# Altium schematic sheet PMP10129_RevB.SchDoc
size 431 x 279 mm; Date: Not shown in title block; ApprovedBy: Not shown in title block; CheckedBy: Not shown in title block; Author: Not shown in title block; CompanyName: Not shown in title block; Engineer: Not shown in title block; Organization: Not shown in title block; Address1: Not shown in title block; Address2: Not shown in title block; Address3: Not shown in title block; Address4: Not shown in title block; DocumentNumber: 1; Revision: Use project parameter SCH_Rev; SheetNumber: 1; SheetTotal: 1; PageSetup: Record=PageOptions¦CenterHorizontal=True¦CenterVertical=True¦PrintScale=1.00¦XCorrection=1.00¦YCorrection=1.00¦PrintKind=0¦BorderSize=5000000¦LeftOffset=0¦BottomOffset=0¦Orientation=2¦PaperLength=1000¦PaperWidth=1000¦Scale=100¦PaperSource=15¦PrintQuality=600¦MediaType=1¦DitherType=10¦PaperKind=Letter¦PrintScaleMode=1
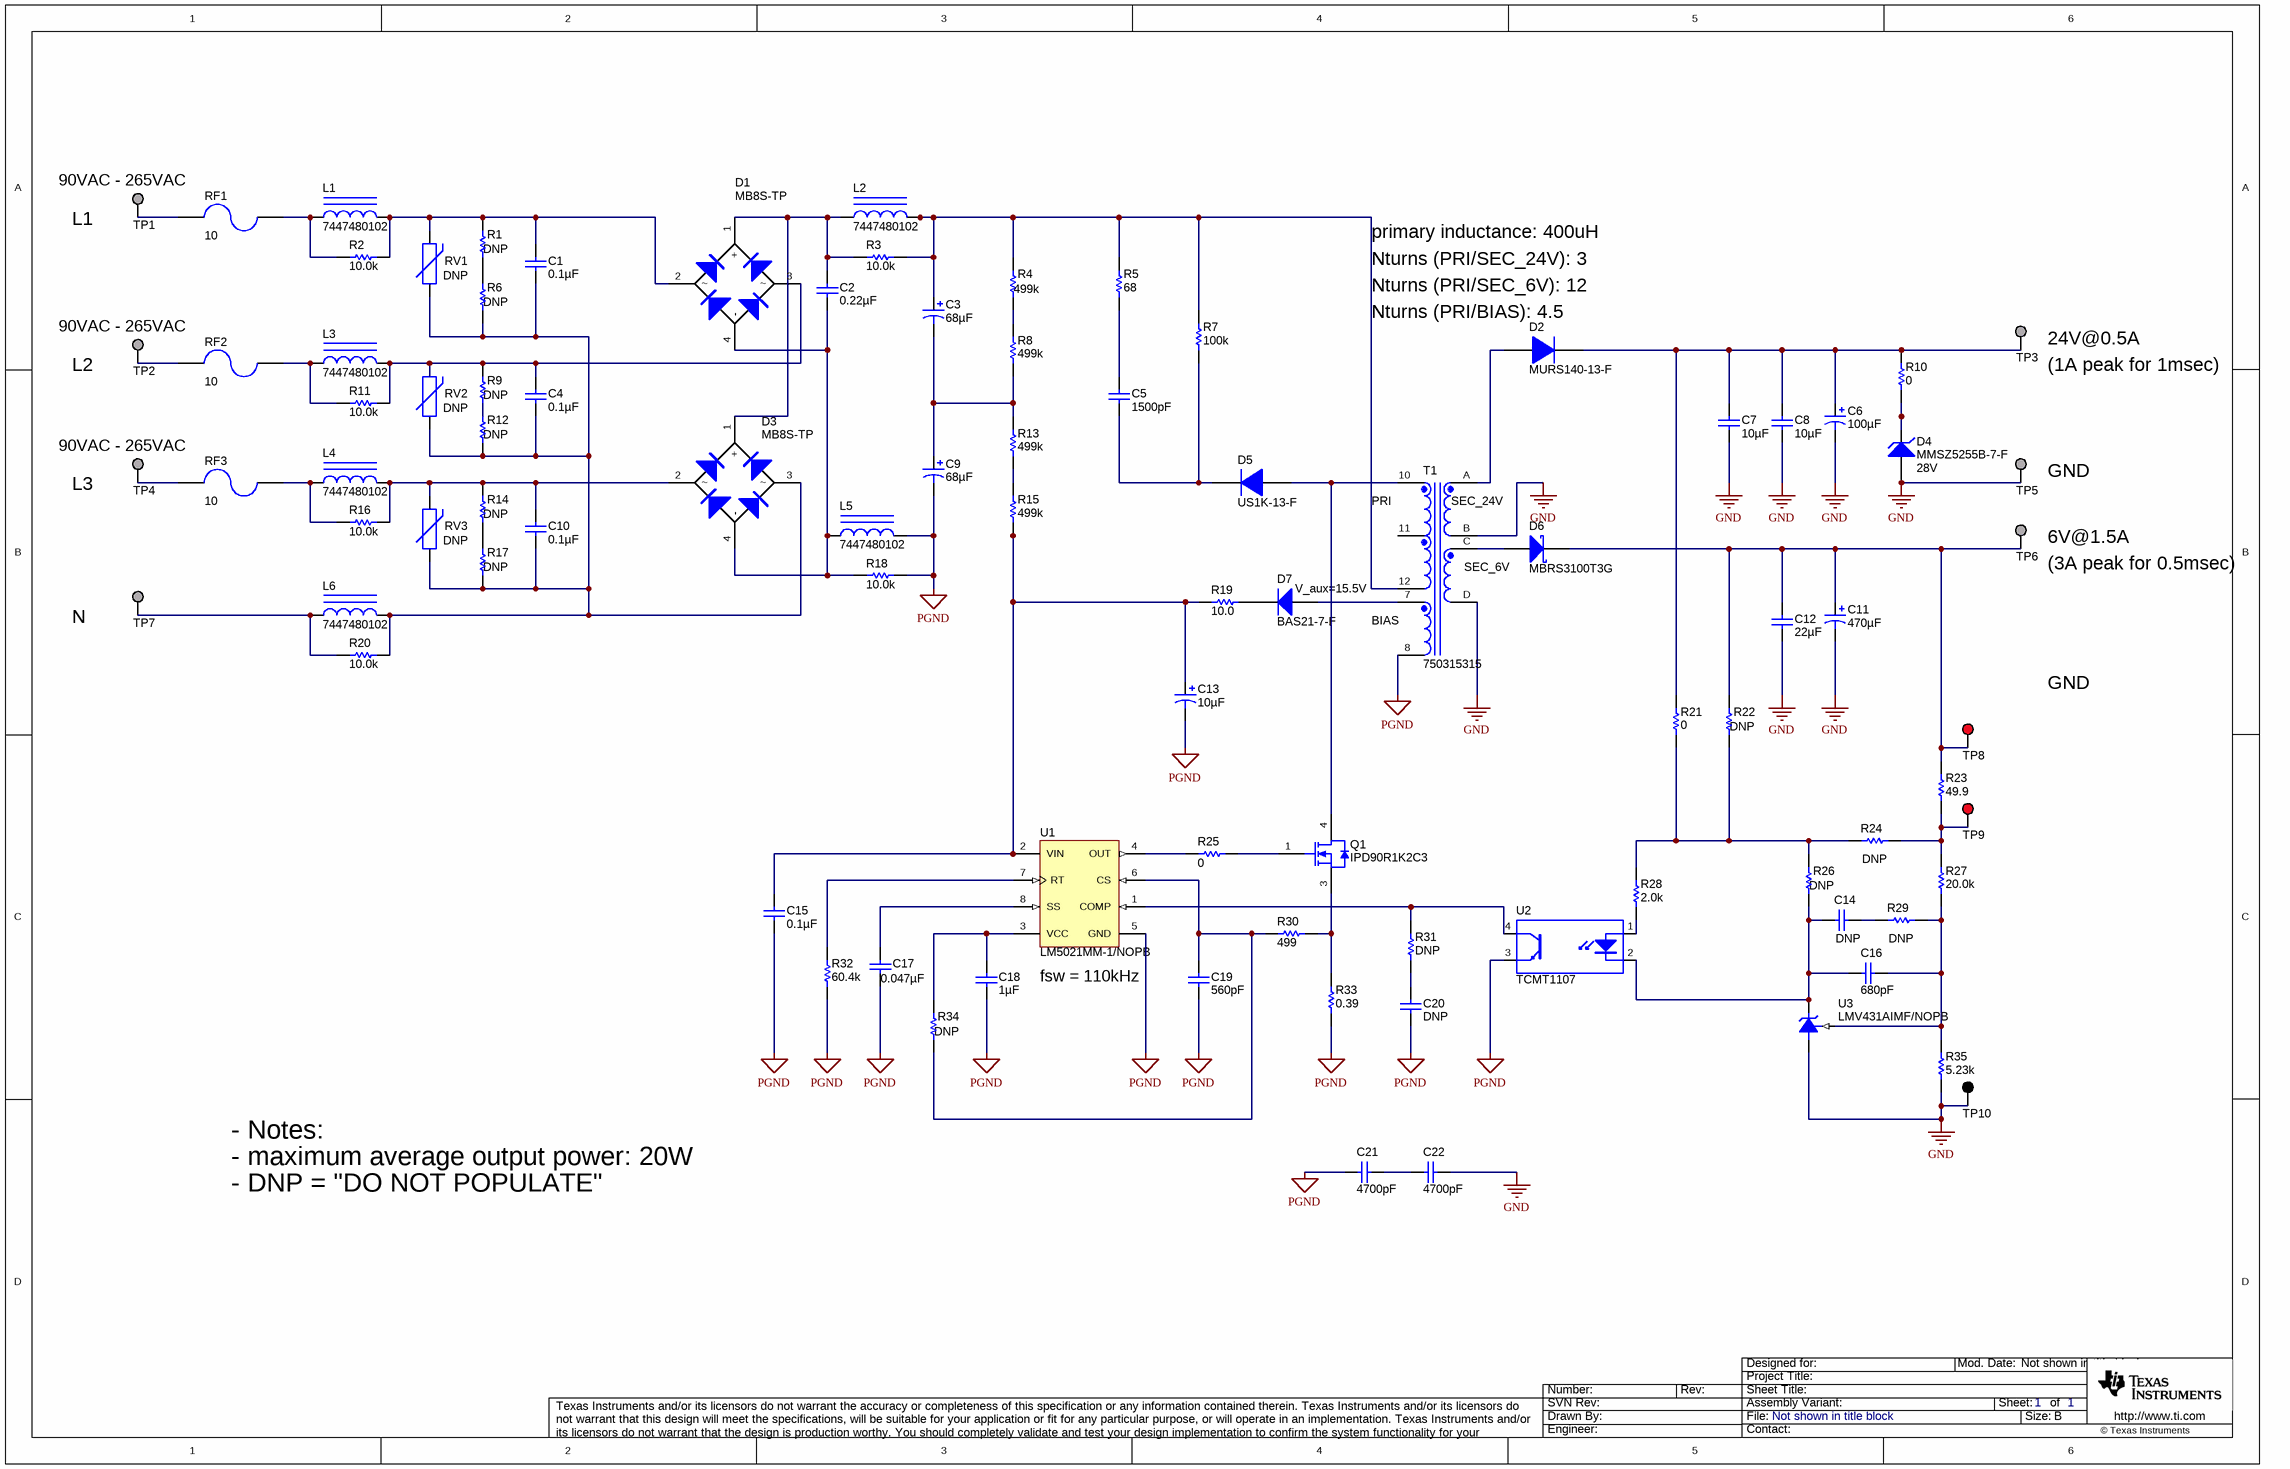
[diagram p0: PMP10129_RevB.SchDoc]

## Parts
C1  ValueDisplayed: 0.1µF  [B32921_1300x1200x600]  (hidden comment: B32921C3104M)
C2  ValueDisplayed: 0.22µF  [B32653_2650x2050x1100]  (hidden comment: B32653A224J)
C3  ValueDisplayed: 68µF  [KXG_1800x3150]  (hidden comment: EKXG401ELL680MM25S)
C4  ValueDisplayed: 0.1µF  [B32921_1300x1200x600]  (hidden comment: B32921C3104M)
C5  ValueDisplayed: 1500pF  [1206]  (hidden comment: C3216C0G2J152J)
C6  ValueDisplayed: 100µF  [SM_RADIAL_F]  (hidden comment: EEE-FK1H101P)
C7  ValueDisplayed: 10µF  [1210_280]  (hidden comment: C3225X7R1H106M250AC)
C8  ValueDisplayed: 10µF  [1210_280]  (hidden comment: C3225X7R1H106M250AC)
C9  ValueDisplayed: 68µF  [KXG_1800x3150]  (hidden comment: EKXG401ELL680MM25S)
C10  ValueDisplayed: 0.1µF  [B32921_1300x1200x600]  (hidden comment: B32921C3104M)
C11  ValueDisplayed: 470µF  [SM_RADIAL_F]  (hidden comment: EEE-FK1A471P)
C12  ValueDisplayed: 22µF  [1210_280]  (hidden comment: C3225X7R1C226K250AC)
C13  ValueDisplayed: 10µF  [SM_RADIAL_D]  (hidden comment: EEE-FC1H100P)
C14  value DNP  [0603_HV]  (hidden comment: Used in BOM report)
C15  ValueDisplayed: 0.1µF  [0603]  (hidden comment: C1608X7R1H104K)
C16  ValueDisplayed: 680pF  [0603]  (hidden comment: C0603C681K5RACTU)
C17  ValueDisplayed: 0.047µF  [0603]  (hidden comment: C1608X7R1H473K)
C18  ValueDisplayed: 1µF  [0805_HV]  (hidden comment: 08055C105KAT2A)
C19  ValueDisplayed: 560pF  [0603]  (hidden comment: GRM1885C1H561JA01D)
C20  value DNP  [0603_HV]  (hidden comment: Used in BOM report)
C21  ValueDisplayed: 4700pF  [VY2_1250x500x1650]  (hidden comment: VY2472M49Y5US63V7)
C22  ValueDisplayed: 4700pF  [VY2_1250x500x1650]  (hidden comment: VY2472M49Y5US63V7)
D1  MB8S-TP  [MBS-1]
D2  MURS140-13-F  [SMB]
D3  MB8S-TP  [MBS-1]
D4  MMSZ5255B-7-F  value 28V  [SOD-123]
D5  US1K-13-F  [SMA]
D6  MBRS3100T3G  [SMC]
D7  BAS21-7-F  [SOT-23]
L1  7447480102  [WE_TI_1014]
L2  7447480102  [WE_TI_1014]
L3  7447480102  [WE_TI_1014]
L4  7447480102  [WE_TI_1014]
L5  7447480102  [WE_TI_1014]
L6  7447480102  [WE_TI_1014]
Q1  IPD90R1K2C3  [DPAK]
R1  value DNP  [0805_HV]  (hidden comment: Used in BOM report)
R2  ValueDisplayed: 10.0k  [0805_HV]  (hidden comment: CRCW080510K0FKEA)
R3  ValueDisplayed: 10.0k  [0805_HV]  (hidden comment: CRCW080510K0FKEA)
R4  ValueDisplayed: 499k  [1206]  (hidden comment: CRCW1206499KFKEA)
R5  ValueDisplayed: 68  [2010]  (hidden comment: CRCW201068R0JNEF)
R6  value DNP  [0805_HV]  (hidden comment: Used in BOM report)
R7  ValueDisplayed: 100k  [2010]  (hidden comment: CRCW2010100KFKEF)
R8  ValueDisplayed: 499k  [1206]  (hidden comment: CRCW1206499KFKEA)
R9  value DNP  [0805]  (hidden comment: Used in BOM report)
R10  ValueDisplayed: 0  [0805_HV]  (hidden comment: CRCW08050000Z0EAHP)
R11  ValueDisplayed: 10.0k  [0805_HV]  (hidden comment: CRCW080510K0FKEA)
R12  value DNP  [0805_HV]  (hidden comment: Used in BOM report)
R13  ValueDisplayed: 499k  [1206]  (hidden comment: CRCW1206499KFKEA)
R14  value DNP  [0805_HV]  (hidden comment: Used in BOM report)
R15  ValueDisplayed: 499k  [1206]  (hidden comment: CRCW1206499KFKEA)
R16  ValueDisplayed: 10.0k  [0805_HV]  (hidden comment: CRCW080510K0FKEA)
R17  value DNP  [0805_HV]  (hidden comment: Used in BOM report)
R18  ValueDisplayed: 10.0k  [0805_HV]  (hidden comment: CRCW080510K0FKEA)
R19  ValueDisplayed: 10.0  [0805_HV]  (hidden comment: CRCW080510R0FKEA)
R20  ValueDisplayed: 10.0k  [0805_HV]  (hidden comment: CRCW080510K0FKEA)
R21  ValueDisplayed: 0  [0603]  (hidden comment: CRCW06030000Z0EA)
R22  value DNP  [0603_HV]  (hidden comment: Used in BOM report)
R23  ValueDisplayed: 49.9  [0603]  (hidden comment: CRCW060349R9FKEA)
R24  value DNP  [0603_HV]  (hidden comment: Used in BOM report)
R25  ValueDisplayed: 0  [0805_HV]  (hidden comment: CRCW08050000Z0EA)
R26  value DNP  [0603_HV]  (hidden comment: Used in BOM report)
R27  ValueDisplayed: 20.0k  [0603]  (hidden comment: CRCW060320K0FKEA)
R28  ValueDisplayed: 2.0k  [0603]  (hidden comment: CRCW06032K00JNEA)
R29  value DNP  [0603_HV]  (hidden comment: Used in BOM report)
R30  ValueDisplayed: 499  [0603]  (hidden comment: RT0603DRE07499RL)
R31  value DNP  [0603_HV]  (hidden comment: Used in BOM report)
R32  ValueDisplayed: 60.4k  [0603]  (hidden comment: CRCW060360K4FKEA)
R33  ValueDisplayed: 0.39  [1206]  (hidden comment: ERJ-8RQFR39V)
R34  value DNP  [0603_HV]  (hidden comment: Used in BOM report)
R35  ValueDisplayed: 5.23k  [0603]  (hidden comment: CRCW06035K23FKEA)
RF1  ValueDisplayed: 10  [RES_PWR4522]  (hidden comment: FW20A10R0JACT-ND)
RF2  ValueDisplayed: 10  [RES_PWR4522]  (hidden comment: FW20A10R0JACT-ND)
RF3  ValueDisplayed: 10  [RES_PWR4522]  (hidden comment: FW20A10R0JACT-ND)
RV1  value DNP  [VAR_S10K275E2]  (hidden comment: S10K275E2)
RV2  value DNP  [VAR_S10K275E2]  (hidden comment: S10K275E2)
RV3  value DNP  [VAR_S10K275E2]  (hidden comment: S10K275E2)
T1  750315315  [Wurth_750315315]
TP1  Suggest using a net name here  [Keystone1503-2]  (value not drawn)
TP2  Suggest using a net name here  [Keystone1503-2]  (value not drawn)
TP3  Suggest using a net name here  [Keystone1503-2]  (value not drawn)
TP4  Suggest using a net name here  [Keystone1503-2]  (value not drawn)
TP5  Suggest using a net name here  [Keystone1503-2]  (value not drawn)
TP6  Suggest using a net name here  [Keystone1503-2]  (value not drawn)
TP7  Suggest using a net name here  [Keystone1503-2]  (value not drawn)
TP8  5000  [Keystone5000]  (value not drawn)
TP9  5000  [Keystone5000]  (value not drawn)
TP10  5001  [Keystone5001]  (value not drawn)
U1  LM5021MM-1/NOPB  [MUA08A_N]
U2  TCMT1107  [SOP-4]
U3  LMV431AIMF/NOPB  [MF03A_N]

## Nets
GND: C6.2(-) C7.2 C8.2 C11.2(-) C12.2 C22.2 D4.2(A) R35.1 T1.B T1.D TP5.1 TP10.1 U3.3(A)
PGND: C9.2(-) C13.2(-) C15.2 C17.2 C18.2 C19.2 C20.2 C21.1 L5.2 R18.2 R32.1 R33.1 T1.8 U1.5(GND) U2.3(E)
NetC1_1: C1.1 D1.2 L1.2 R1.2 R2.2 RV1.2
NetC1_2: C1.2 C4.2 C10.2 D3.3 L6.2 R6.1 R12.1 R17.1 R20.2 RV1.1 RV2.1 RV3.1
NetC2_1: C2.1 D1.1(+) D3.1(+) L2.1 R3.1
NetC2_2: C2.2 D1.4(-) D3.4(-) L5.1 R18.1
NetC3_1: C3.1(+) L2.2 R3.2 R4.2 R5.2 R7.2 T1.12
NetC3_2: C3.2(-) C9.1(+) R8.1 R13.2
NetC4_1: C4.1 D1.3 L3.2 R9.2 R11.2 RV2.2
NetC5_1: C5.1 R5.1
NetC5_2: C5.2 D5.1(K) R7.1
NetC6_1: C6.1(+) C7.1 C8.1 D2.1(K) R10.2 R21.2 TP3.1
NetC10_1: C10.1 D3.2 L4.2 R14.2 R16.2 RV3.2
NetC11_1: C11.1(+) C12.1 D6.1(K) R22.2 R23.2 TP6.1 TP8.1
NetC13_1: C13.1(+) C15.1 R15.1 R19.1 U1.2(VIN)
NetC14_1: C14.1 R29.1
NetC14_2: C14.2 C16.2 R26.1 U2.2(K) U3.2(K)
NetC16_1: C16.1 R27.1 R29.2 R35.2 U3.1(REF)
NetC17_1: C17.1 U1.8(SS)
NetC18_1: C18.1 R34.2 U1.3(VCC)
NetC19_1: C19.1 R30.1 R34.1 U1.6(CS)
NetC20_1: C20.1 R31.1
NetC21_2: C21.2 C22.1
NetD2_2: D2.2(A) T1.A
NetD4_1: D4.1(K) R10.1
NetD5_2: D5.2(A) Q1.4(D) T1.10
NetD6_2: D6.2(A) T1.C
NetD7_1: D7.1(A) T1.7
NetD7_3: D7.3(K) R19.2
NetL1_1: L1.1 R2.1 RF1.1
NetL3_1: L3.1 R11.1 RF2.1
NetL4_1: L4.1 R16.1 RF3.1
NetL6_1: L6.1 R20.1 TP7.1
NetQ1_1: Q1.1(G) R25.2
NetQ1_3: Q1.3(S) R30.2 R33.2
NetR1_1: R1.1 R6.2
NetR4_1: R4.1 R8.2
NetR9_1: R9.1 R12.2
NetR13_1: R13.1 R15.2
NetR14_1: R14.1 R17.2
NetR21_1: R21.1 R22.1 R24.1 R26.2 R28.2
NetR23_1: R23.1 R24.2 R27.2 TP9.1
NetR25_1: R25.1 U1.4(OUT)
NetR28_1: R28.1 U2.1(A)
NetR31_2: R31.2 U1.1(COMP) U2.4(C)
NetR32_2: R32.2 U1.7(RT)
NetRF1_2: RF1.2 TP1.1
NetRF2_2: RF2.2 TP2.1
NetRF3_2: RF3.2 TP4.1

Not connected (* = marked no-connect by the designer): T1 11

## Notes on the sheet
- (near TP1) 90VAC - 265VAC
- (near TP1) L1
- primary inductance: 400uH
- Nturns (PRI/SEC_24V): 3
- Nturns (PRI/SEC_6V): 12
- (near TP2) 90VAC - 265VAC
- (near D2) Nturns (PRI/BIAS): 4.5
- (near TP3) 24V@0.5A
- (near TP2) L2
- (near TP3) (1A peak for 1msec)
- (near TP4) 90VAC - 265VAC
- (near TP4) L3
- (near TP5) GND
- (near T1) PRI
- (near T1) SEC_24V
- (near TP6) 6V@1.5A
- N
- (near D7) V_aux=15.5V
- (near T1) BIAS
- (near T1) SEC_6V
- (near TP6) (3A peak for 0.5msec)
- GND
- fsw = 110kHz
- - Notes:
- - maximum average output power: 20W
- - DNP = "DO NOT POPULATE"

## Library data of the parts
C1 C4 C10 = B32921C3104M: CAP, Film, 0.1 µF, 305 V, +/- 20%, TH; Manufacturer: EPCOS Inc; Polarized: N; CompType: Capacitor; Value: 0.1uF; U/M: EA; Cap_F: 0.0000001; Tolerance_%: 20; Value1: Unknown; VDC_V: 305; Value2: 305V; TaMin_C: -40; TaMax_C: 110; Cap_Case: 13x12x6mm
C2 = B32653A224J: CAP, Film, 0.22 µF, 1000 V, +/- 5%, TH; Manufacturer: EPCOS Inc; Polarized: N; CompType: Capacitor; Value: 0.22uF; U/M: EA; Cap_F: 0.00000022; Tolerance_%: 5; Value1: Unknown; VDC_V: 1000; Value2: 1000V; TaMin_C: -55; TaMax_C: 110; Cap_Case: 26.5x20.5x11mm
C3 C9 = EKXG451ELL680MMN3S: CAP, AL, 68 µF, 400 V, +/- 20%,  ohm, TH; Manufacturer: Chemi-Con; Polarized: Y; CompType: Capacitor; Value: 68uF; U/M: EA; Cap_F: 0.000068; Tolerance_%: 20; Value1: Unknown; VDC_V: 450; Value2: 400V; IRMS_A: 0.63; TaMin_C: -25; TaMax_C: 105; Cap_Case: 18x31.5mm
C5 = C3216C0G2J152J: CAP, CERM, 1500 pF, 630 V, +/- 5%, C0G/NP0, 1206; Manufacturer: TDK; Polarized: N; CompType: Capacitor; Value: 1500pF; U/M: EA; Cap_F: 0.0000000015; Tolerance_%: 5; ESR_ohm: 0.0467; Value1: 0.0467 ohm; VDC_V: 630; Value2: 630V; TaMin_C: -55; TaMax_C: 125
C6 = EEE-FK1H101P: CAP, AL, 100 µF, 50 V, +/- 20%, 0.34 ohm, SMD; Manufacturer: Panasonic; Polarized: Y; CompType: Capacitor; Value: 100uF; U/M: EA; Cap_F: 0.0001; Tolerance_%: 20; VDC_V: 50; Value2: 50V; ESR_ohm: 0.34; IRMS_A: 0.35; TaMin_C: -55; TaMax_C: 105; Cap_Case: F
C7 C8 = C3225X7R1H106M250AC: CAP, CERM, 10 µF, 50 V, +/- 20%, X7R, 1210; Manufacturer: TDK; Polarized: N; CompType: Capacitor; Value: 10uF; U/M: EA; Cap_F: 0.00001; Tolerance_%: 20; Value1: Unknown; VDC_V: 50; Value2: 50V; TaMin_C: -55; TaMax_C: 125; Cap_Case: 1210
C11 = EEE-FK1A471P: CAP, AL, 470 µF, 10 V, +/- 20%, 0.16 ohm, SMD; Manufacturer: Panasonic; Polarized: Y; CompType: Capacitor; Value: 470uF; U/M: EA; Cap_F: 0.00047; Tolerance_%: 20; VDC_V: 10; Value2: 10V; ESR_ohm: 0.16; IRMS_A: 0.6; TaMin_C: -55; TaMax_C: 105; Cap_Case: F
C12 = C3225X7R1C226K250AC: CAP, CERM, 22 µF, 16 V, +/- 10%, X7R, 1210; Manufacturer: TDK; Polarized: N; CompType: Capacitor; Value: 22uF; U/M: EA; Cap_F: 0.000022; Tolerance_%: 10; Value1: Unknown; VDC_V: 16; Value2: 16V; TaMin_C: -55; TaMax_C: 125; Cap_Case: 1210
C13 = EEE-FC1H100P: CAP, AL, 10 µF, 50 V, +/- 20%, 2 ohm, SMD; Manufacturer: Panasonic; Polarized: Y; CompType: Capacitor; Value: 10uF; U/M: EA; Cap_F: 0.00001; Tolerance_%: 20; Value1: 2 ohm; VDC_V: 50; Value2: 50V; ESR_ohm: 2; IRMS_A: 0.07; TaMin_C: -40; TaMax_C: 105; Cap_Case: D
C14 C20 = Capacitor: CAP, CERM, xxxF, xxV, [TempCo], xx%, [PackageReference]; Polarized: N; U/M: EA
C15 = C1608X7R1H104K: CAP, CERM, 0.1 µF, 50 V, +/- 10%, X7R, 0603; Manufacturer: TDK; Polarized: N; CompType: Capacitor; Value: 0.1uF; U/M: EA; Cap_F: 0.0000001; Tolerance_%: 10; ESR_ohm: 0.017; Value1: 0.017 ohm; VDC_V: 50; Value2: 50V; TaMin_C: -55; TaMax_C: 125
C16 = C0603C681K5RACTU: CAP, CERM, 680 pF, 50 V, +/- 10%, X7R, 0603; Manufacturer: Kemet; Polarized: N; CompType: Capacitor; Value: 680pF; U/M: EA; Cap_F: 0.00000000068; Tolerance_%: 10; Value1: Unknown; VDC_V: 50; Value2: 50V; TaMin_C: -55; TaMax_C: 125; AEC Category: Q200
C17 = C1608X7R1H473K: CAP, CERM, 0.047 µF, 50 V, +/- 10%, X7R, 0603; Manufacturer: TDK; Polarized: N; CompType: Capacitor; Value: 0.047uF; U/M: EA; Cap_F: 0.000000047; Tolerance_%: 10; ESR_ohm: 0.0234; Value1: 0.0234 ohm; VDC_V: 50; Value2: 50V; TaMin_C: -55; TaMax_C: 125
C18 = 08055C105KAT2A: CAP, CERM, 1 µF, 50 V, +/- 10%, X7R, 0805; Manufacturer: AVX; Polarized: N; CompType: Capacitor; Value: 1uF; U/M: EA; Cap_F: 0.000001; Tolerance_%: 10; Value1: Unknown; VDC_V: 50; Value2: 50V; TaMin_C: -55; TaMax_C: 125; Cap_Case: 0805
C19 = GRM1885C1H561JA01D: CAP, CERM, 560 pF, 50 V, +/- 5%, C0G/NP0, 0603; Manufacturer: MuRata; Polarized: N; CompType: Capacitor; Value: 560pF; U/M: EA; Cap_F: 0.00000000056; Tolerance_%: 5; Value1: Unknown; VDC_V: 50; Value2: 50V; TaMin_C: -55; TaMax_C: 125
C21 C22 = VY2472M49Y5US63V7: CAP, CERM, 4700 pF, 440 V, +/- 20%, Y5U, TH, 12.5x5mm; Manufacturer: Vishay-Bccomponents; Polarized: N; CompType: Capacitor; Value: 4700pF; U/M: EA; Cap_F: 0.0000000047; Tolerance_%: 20; Value1: Unknown; VDC_V: 440; Value2: 440V; TaMin_C: -40; TaMax_C: 125; Cap_Case: 12.5x5x16.5
D1 D3 = MB8S-TP: Diode, Switching-Bridge, 800 V, 0.5 A, 4-Pin TO269AA, Body 4.95 x 4.2 mm, Pitch 2.555 mm; Manufacturer: Micro Commercial Components; U/M: EA; Vf_V: 1; Value: 800V; Value1: 0.5A; Value2: 1V; Io_A: 0.5; Vr_V: 800; TJmax_C: 150
D2 = MURS140-13-F: Diode, Ultrafast, 400 V, 1 A, SMB; Manufacturer: Diodes Inc.; U/M: EA; Vf_V: 1.25; Value: 400V; Value1: 1A; Value2: 1.25V; Io_A: 1; Vr_V: 400; TJmax_C: 150; RJC_CperW: 13
D4 = MMSZ5255B-7-F: Diode, Zener, 28 V, 500 mW, SOD-123; Manufacturer: Diodes Inc.; SymbolCreator: a0412235; U/M: EA; Power_W: 0.5; Vz_V: 28; Value1: 0.5W; RJA_CperW: 350
D5 = US1K-13-F: Diode, Fast Rectifier, 800 V, 1 A, SMA; Manufacturer: Diodes Inc.; U/M: EA; Vf_V: 1.7; Value: 800V; Value1: 1A; Value2: 1.7V; Io_A: 1; Vr_V: 800; TJmax_C: 150
D6 = MBRS3100T3G: Diode, Schottky, 100 V, 3 A, SMC; Manufacturer: ON Semiconductor; U/M: EA; Vf_V: 0.62; Value: 100V; Value1: 3A; Value2: 0.62V; Io_A: 3; Vr_V: 100; TJmax_C: 150; RJC_CperW: 11
D7 = BAS21-7-F: Diode, Switching, 200 V, 0.2 A, SOT-23; Manufacturer: Diodes Inc.; U/M: EA; Vf_V: 1.25; Value: 200V; Value1: 0.2A; Value2: 1.25V; Io_A: 0.2; Vr_V: 200; TJmax_C: 150; RJC_CperW: 500
L1-L6 = 7447480471: Inductor, Wirewound, Ferrite, 470 µH, 1.15 A, 0.47 ohm, TH; Manufacturer: Wurth Elektronik; Value: 1000uH; ValueDisplayed: 1000µH; Imax_A: 1.15; Irms: 1.15A @ 40C rise; Isat: 1.15A @ 10% inductance drop; DCR_ohm: 0.47
Q1 = MOSFET_N_D4G1S3: MOSFET, N-CH, xxV, xxxA, DPAK; Manufacturer: Used in BOM report; U/M: EA
R1 R6 R9 R12 R14 R17 R22 R24 R26 R29 R31 R34 = Resistor: RES, xxx ohm, x%, xW, [PackageReference]; U/M: EA
R2 R3 R11 R16 R18 R20 = CRCW080510K0FKEA: RES, 10.0 k, 1%, 0.125 W, 0805; Manufacturer: Vishay-Dale; CompType: Resistor; Value: 10.0k; Res_ohm: 10000; Value_Code: 10k0; Tolerance_%: 1; Power_W: 0.125; Value2: 0.125W; VDC_V: 150; TempCo: 100 ppm/C; EIA_Code: E96; U/M: EA
R4 R8 R13 R15 = CRCW1206499KFKEA: RES, 499 k, 1%, 0.25 W, 1206; Manufacturer: Vishay-Dale; CompType: Resistor; Value: 499k; Res_ohm: 499000; Tolerance_%: 1; Power_W: 0.25; Value2: 0.25W; VDC_V: 200; TempCo: 100 ppm/C; EIA_Code: E96; U/M: EA
R5 = CRCW201068R0JNEF: RES, 68, 5%, 0.75 W, 2010; Manufacturer: Vishay-Dale; CompType: Resistor; Value: 68; Value_Code: 68R0; Tolerance_%: 5; Power_W: 0.75; Value2: 0.75W; VDC_V: 400; TempCo: 200 ppm/C; EIA_Code: E24; U/M: EA; AEC Category: Q200
R7 = CRCW2010100KFKEF: RES, 100 k, 1%, 0.75 W, 2010; Manufacturer: Vishay-Dale; CompType: Resistor; Value: 100k; Res_ohm: 100000; Tolerance_%: 1; Power_W: 0.75; Value2: 0.75W; VDC_V: 400; TempCo: 100 ppm/C; EIA_Code: E96; U/M: EA; AEC Category: Q200
R10 = CRCW08050000Z0EAHP: RES, 0, 5%, 0.333 W, 0805; Manufacturer: Vishay-Dale; CompType: Resistor; Value: 0; Value_Code: 0000; Tolerance_%: 5; Power_W: 0.333; Value2: 0.333W; TempCo: 200 ppm/C; EIA_Code: E24; U/M: EA
R19 = CRCW080510R0FKEA: RES, 10.0, 1%, 0.125 W, 0805; Manufacturer: Vishay-Dale; CompType: Resistor; Value: 10.0; Res_ohm: 10; Value_Code: 10R0; Tolerance_%: 1; Power_W: 0.125; Value2: 0.125W; VDC_V: 150; TempCo: 100 ppm/C; EIA_Code: E96; U/M: EA
R21 = CRCW06030000Z0EA: RES, 0, 5%, 0.1 W, 0603; Manufacturer: Vishay-Dale; CompType: Resistor; Value: 0; Value_Code: 0000; Tolerance_%: 5; Power_W: 0.1; Value2: 0.1W; VDC_V: 75; TempCo: 200 ppm/C; EIA_Code: E24; U/M: EA
R23 = CRCW060349R9FKEA: RES, 49.9, 1%, 0.1 W, 0603; Manufacturer: Vishay-Dale; CompType: Resistor; Value: 49.9; Value_Code: 49R9; Tolerance_%: 1; Power_W: 0.1; Value2: 0.1W; VDC_V: 75; TempCo: 100 ppm/C; EIA_Code: E96; U/M: EA
R25 = CRCW08050000Z0EA: RES, 0, 5%, 0.125 W, 0805; Manufacturer: Vishay-Dale; CompType: Resistor; Value: 0; Value_Code: 0000; Tolerance_%: 5; Power_W: 0.125; Value2: 0.125W; VDC_V: 150; TempCo: 200 ppm/C; EIA_Code: E24; U/M: EA
R27 = CRCW060320K0FKEA: RES, 20.0 k, 1%, 0.1 W, 0603; Manufacturer: Vishay-Dale; CompType: Resistor; Value: 20.0k; Res_ohm: 20000; Value_Code: 20k0; Tolerance_%: 1; Power_W: 0.1; Value2: 0.1W; VDC_V: 75; TempCo: 100 ppm/C; EIA_Code: E96; U/M: EA
R28 = CRCW06032K00JNEA: RES, 2.0 k, 5%, 0.1 W, 0603; Manufacturer: Vishay-Dale; CompType: Resistor; Value: 2.0k; Res_ohm: 2000; Value_Code: 2k00; Tolerance_%: 5; Power_W: 0.1; Value2: 0.1W; VDC_V: 75; TempCo: 200 ppm/C; EIA_Code: E24; U/M: EA
R30 = RT0603DRE07499RL: RES, 499, 0.5%, 0.1 W, 0603; Manufacturer: Yageo America; CompType: Resistor; Value: 499; Value_Code: 499R; Tolerance_%: 0.5; Power_W: 0.1; Value2: 0.1W; VDC_V: 75; TempCo: 50 ppm/C; EIA_Code: E192; U/M: EA
R32 = CRCW060360K4FKEA: RES, 60.4 k, 1%, 0.1 W, 0603; Manufacturer: Vishay-Dale; CompType: Resistor; Value: 60.4k; Res_ohm: 60400; Value_Code: 60k4; Tolerance_%: 1; Power_W: 0.1; Value2: 0.1W; VDC_V: 75; TempCo: 100 ppm/C; EIA_Code: E96; U/M: EA
R33 = ERJ-8RQFR39V: RES, 0.39, 1%, 0.25 W, 1206; Manufacturer: Panasonic; CompType: Resistor; Value: 0.39; Value_Code: R390; Tolerance_%: 1; Power_W: 0.25; Value2: 0.25W; TempCo: 250 ppm/C; EIA_Code: E96; U/M: EA; AEC Category: Q200
R35 = CRCW06035K23FKEA: RES, 5.23 k, 1%, 0.1 W, 0603; Manufacturer: Vishay-Dale; CompType: Resistor; Value: 5.23k; Res_ohm: 5230; Value_Code: 5k23; Tolerance_%: 1; Power_W: 0.1; Value2: 0.1W; VDC_V: 75; TempCo: 100 ppm/C; EIA_Code: E96; U/M: EA
RF1 = PWR4522AS10R0JA: RES, 10, 5%, 32W, Fusible, TH; Manufacturer: Bourns; SymbolCreator: a0412235; CompType: Fusible Resistor; Value: 10; Value_Code: 10R0; Tolerance_%: 5; Power_W: 3; Value2: 3W; TempCo: 90 ppm/C; EIA_Code: E24; U/M: EA
RF2 RF3 = PWR4522AS10R0JA: RES, 10, 5%, 2 W, Fusible, TH; Manufacturer: Bourns; SymbolCreator: a0412235; CompType: Fusible Resistor; Value: 10; Value_Code: 10R0; Tolerance_%: 5; Power_W: 3; Value2: 3W; TempCo: 90 ppm/C; EIA_Code: E24; U/M: EA
RV1-RV3 = S10K275E2: Varistor 275V RMS 10MM Radial, TH; Manufacturer: EPCOS Inc; SymbolCreator: a0412235
T1 = 750315315: Transformer, 400 uH, TH; Manufacturer: Wurth Elektronik; SymbolCreator: Altium; DCR_Ohm: 0.305; Value: 400 uH; LeakageL: 7 uH; Imax_A: 1.6; U/M: EA
TP1-TP7 = 1503-2: Terminal, Turret, TH, Double; Manufacturer: Keystone; CompType: Turret Terminal; U/M: EA
TP8 TP9 = 5000: Test Point, Miniature, Red, TH; Manufacturer: Keystone; CompType: Test Point Loop; U/M: EA
TP10 = 5001: Test Point, Miniature, Black, TH; Manufacturer: Keystone; CompType: Test Point Loop; U/M: EA
U1 = LM5021MM-1/NOPB: AC-DC Current Mode PWM Controller, 8-pin MSOP, Pb-Free; Manufacturer: Texas Instruments; PackageTopMarking: ZXTT*21-1; PowerWise: N; CompType: Switcher
U2 = TCMT1107: Optocoupler, 3.75kV RMS, SMT; Manufacturer: Vishay-Semiconductor; U/M: EA
U3 = LMV431AIMF/NOPB: Low-Voltage (1.24V) Adjustable Precision Shunt Regulators, 3-pin SOT-23, Pb-Free; Manufacturer: Texas Instruments; PackageTopMarking: RLA*XTT; PowerWise: N; CompType: MiscPower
